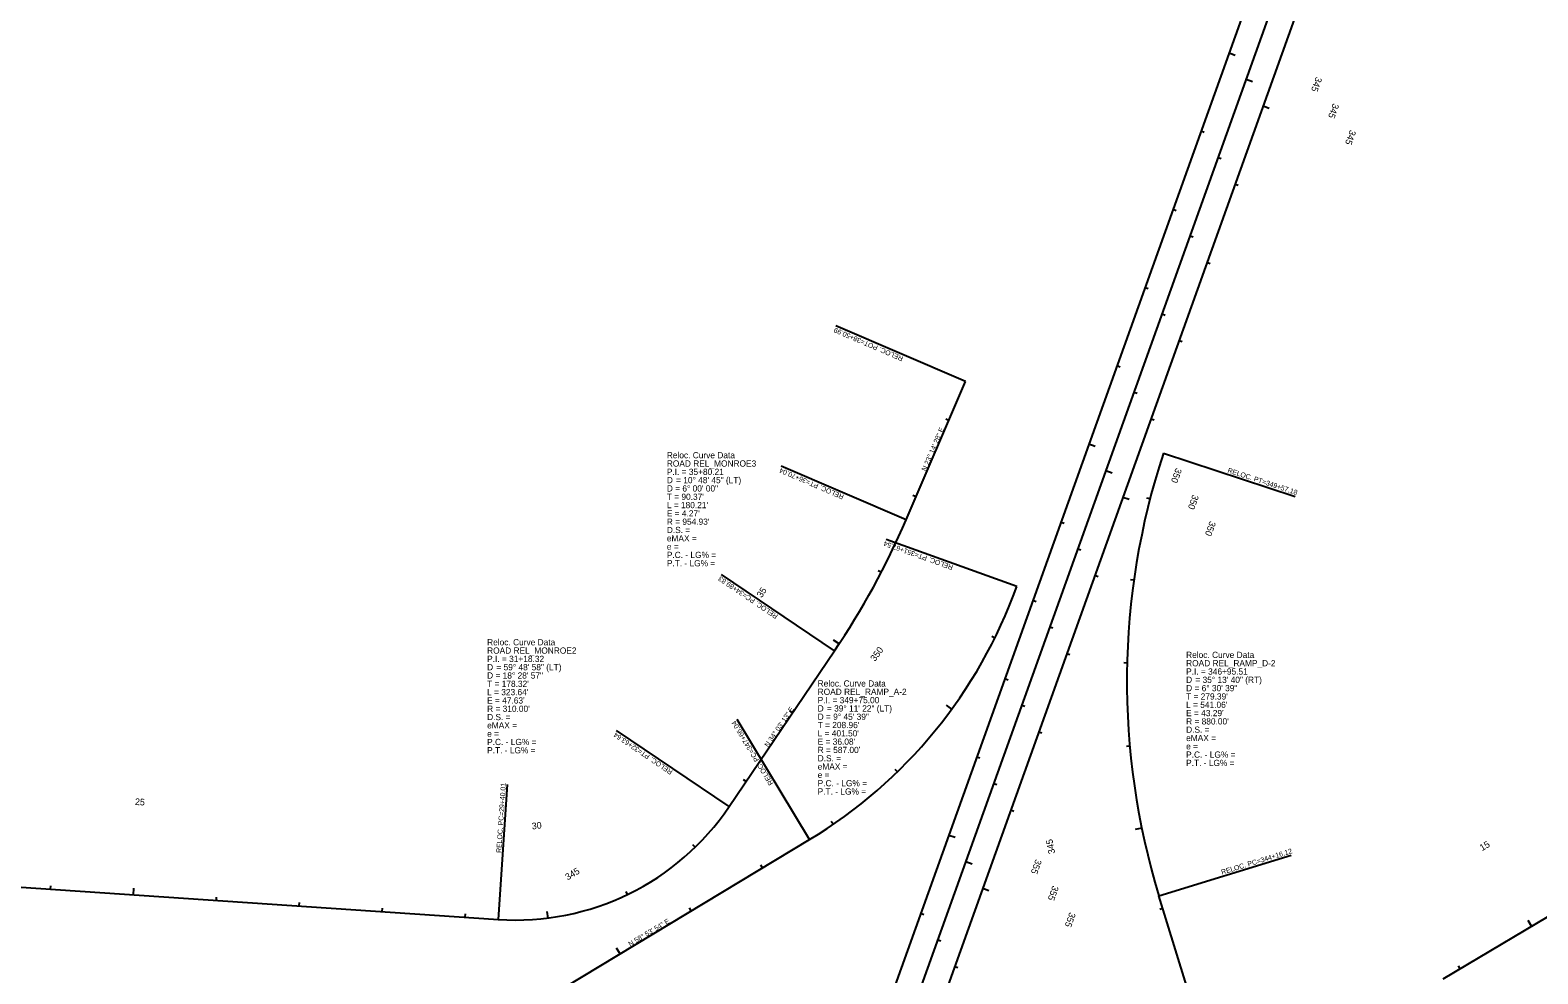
# Model space of a CAD drawing. Extents: x 1902569 to 1961902, y 757103 to 798350.
# Drawn here: x 1940075 to 1941889, y 781155 to 782290 of the extents above; entities that cross this region are included whole.
import ezdxf

# ---------------------------------------------------------------- set-up
doc = ezdxf.new("R2010")
doc.units = 0
for name, color, linetype in [('RD_HC_CL_Rel', 7, 'Continuous'), ('RD_HC_Data_Rel', 7, 'Continuous'), ('RD_HC_Data_Tic_Rel', 7, 'Continuous'), ('RD_HC_TX_Rel_Sta50', 7, 'Continuous')]:
    doc.layers.add(name, color=color, linetype=linetype)

msp = doc.modelspace()

# ---------------------------------------------------------------- linework, layer by layer
at = {"layer": 'RD_HC_CL_Rel'}
for p, q in [((1941878, 783269.7), (1940313.2, 778901.6)), ((1941633, 782497), (1940341.4, 778891.4)), ((1941661.2, 782486.8), (1940101.7, 778133.2)), ((1941128.7, 781701), (1941200.1, 781867.3)), ((1940915.8, 781355.7), (1941042.5, 781543.1)), ((1941774.7, 781148.4), (1942162.1, 781379.3)), ((1939412.5, 781302.9), (1940638.1, 781220)), ((1940629.7, 781085.3), (1941012.4, 781316.1)), ((1941538.5, 780904.1), (1941432.9, 781248.5))]:
    msp.add_line(p, q, dxfattribs=at)
for centre, radius, start, end in [((1942274.3, 781506.4), 880, 161.8185, 197.0463), ((1940251.3, 782077.8), 954.9, 325.9463, 336.7589), ((1940709.2, 781818.7), 587, 301.1016, 340.2909), ((1940659, 781529.3), 310, 266.1303, 325.9463)]:
    msp.add_arc(centre, radius, start, end, dxfattribs=at)
at = {"layer": 'RD_HC_Data_Rel'}
for p, q in [((1941200.1, 781867.3), (1941044.3, 781934.2)), ((1941438.2, 781781), (1941596.6, 781729)), ((1941128.7, 781701), (1940978.4, 781765.5)), ((1941261.8, 781620.8), (1941104.7, 781677)), ((1941042.5, 781543.1), (1940906.5, 781634.9)), ((1940915.8, 781355.7), (1940780.3, 781447.3)), ((1941012.4, 781316.1), (1940925.3, 781460.5)), ((1940638.1, 781220), (1940649, 781382.4)), ((1941432.9, 781248.5), (1941592, 781297.2))]:
    msp.add_line(p, q, dxfattribs=at)
at = {"layer": 'RD_HC_Data_Tic_Rel'}
for p, q in [((1941517.3, 782262.9), (1941524.8, 782260.2)), ((1941537.7, 782231), (1941545.3, 782228.3)), ((1941558.1, 782199), (1941565.7, 782196.3)), ((1941483.6, 782168.8), (1941487.3, 782167.5)), ((1941504, 782136.9), (1941507.8, 782135.5)), ((1941524.4, 782104.9), (1941528.2, 782103.6)), ((1941449.9, 782074.7), (1941453.6, 782073.3)), ((1941470.3, 782042.7), (1941474, 782041.4)), ((1941490.7, 782010.8), (1941494.5, 782009.4)), ((1941416.1, 781980.5), (1941419.9, 781979.2)), ((1941436.6, 781948.6), (1941440.3, 781947.2)), ((1941457, 781916.6), (1941460.7, 781915.3)), ((1941382.4, 781886.4), (1941386.2, 781885)), ((1941402.8, 781854.4), (1941406.6, 781853.1)), ((1941180, 781820.4), (1941176.3, 781822)), ((1941423.2, 781822.5), (1941427, 781821.1)), ((1941348.7, 781792.2), (1941356.2, 781789.5)), ((1941369.1, 781760.3), (1941376.6, 781757.6)), ((1941140.6, 781728.5), (1941136.9, 781730.1)), ((1941389.5, 781728.3), (1941397.1, 781725.6)), ((1941422.2, 781726.1), (1941418.3, 781727.1)), ((1941315, 781698.1), (1941318.7, 781696.7)), ((1941335.4, 781666.1), (1941339.1, 781664.8)), ((1941098.8, 781637.7), (1941095.2, 781639.5)), ((1941355.8, 781634.2), (1941359.6, 781632.8)), ((1941402.7, 781628.1), (1941398.8, 781628.7)), ((1941281.2, 781604), (1941285, 781602.6)), ((1941301.7, 781572), (1941305.4, 781570.7)), ((1941048.1, 781551.5), (1941041.4, 781555.9)), ((1941235.4, 781558.6), (1941231.8, 781560.4)), ((1941322.1, 781540.1), (1941325.8, 781538.7)), ((1941394.6, 781528.5), (1941390.6, 781528.6)), ((1941247.5, 781509.8), (1941251.3, 781508.5)), ((1940992.2, 781468.7), (1940988.9, 781470.9)), ((1941183.7, 781473.2), (1941177.2, 781477.9)), ((1941267.9, 781477.9), (1941271.7, 781476.5)), ((1941288.3, 781445.9), (1941292.1, 781444.6)), ((1941397.7, 781428.6), (1941393.7, 781428.2)), ((1941213.8, 781415.7), (1941217.5, 781414.3)), ((1941118.2, 781397.7), (1941115.4, 781400.6)), ((1940936.2, 781385.8), (1940932.9, 781388)), ((1941234.2, 781383.7), (1941238, 781382.4)), ((1941040.9, 781334.5), (1941038.7, 781337.8)), ((1941254.6, 781351.8), (1941258.4, 781350.4)), ((1941180.1, 781321.5), (1941187.6, 781318.8)), ((1941412.2, 781329.7), (1941404.4, 781328.1)), ((1940875, 781307), (1940872.2, 781309.8)), ((1940955.8, 781282), (1940953.8, 781285.4)), ((1941200.5, 781289.6), (1941208, 781286.9)), ((1940099.3, 781256.4), (1940099.5, 781260.4)), ((1940199, 781249.7), (1940199.6, 781257.7)), ((1940298.8, 781242.9), (1940299.1, 781246.9)), ((1940793.4, 781249.9), (1940791.7, 781253.5)), ((1941220.9, 781257.6), (1941228.4, 781254.9)), ((1940398.6, 781236.2), (1940398.9, 781240.2)), ((1940498.4, 781229.4), (1940498.6, 781233.4)), ((1940598.1, 781222.7), (1940598.4, 781226.7)), ((1940697.9, 781221.7), (1940696.9, 781229.7)), ((1940870.2, 781230.3), (1940868.1, 781233.8)), ((1941146.3, 781227.4), (1941150.1, 781226)), ((1941437.7, 781233), (1941433.8, 781231.9)), ((1941881.2, 781211.9), (1941877.1, 781218.7)), ((1941166.8, 781195.4), (1941170.5, 781194.1)), ((1940784.6, 781178.7), (1940780.4, 781185.5)), ((1941187.2, 781163.5), (1941190.9, 781162.1)), ((1941795.3, 781160.7), (1941793.3, 781164.1))]:
    msp.add_line(p, q, dxfattribs=at)

# ---------------------------------------------------------------- texts
at = {"layer": 'RD_HC_Data_Rel'}
for s, rotation, p in [('RELOC. POT=38+50.99', 156.7589, (1941125.8, 781897)), ('N 23° 14\' 28" E', 66.7589, (1941152.5, 781758.9)), ('RELOC. PT=36+70.04', 156.7589, (1941054.4, 781730.7)), ('RELOC. PT=349+57.18', 341.8185, (1941514.9, 781758)), ('RELOC. PT=351+67.54', 160.2909, (1941185.8, 781645.9)), ('RELOC. PC=34+89.83', 145.9463, (1940975.1, 781586.2)), ('N 34° 03\' 13" E', 55.9463, (1940962.7, 781426.8)), ('RELOC. PC=347+66.04', 121.1016, (1940969.3, 781383.6)), ('RELOC. PT=32+63.64', 145.9463, (1940848.4, 781398.8)), ('RELOC. PC=29+40.01', 86.1303, (1940641.5, 781299.9)), ('RELOC. PC=344+16.12', 17.0463, (1941508.8, 781273.8)), ('N 58° 53\' 54" E', 31.1016, (1940796.7, 781187.2))]:
    msp.add_text(s, height=6, rotation=rotation, dxfattribs=at).set_placement(p)
for s, p in [('Reloc. Curve Data', (1940840.8, 781774.9)), ('ROAD REL_MONROE3', (1940840.8, 781764.9)), ('P.I. = 35+80.21', (1940840.8, 781754.9)), ('D', (1940840.8, 781744.9)), ('    = 10° 48\' 45" (LT)', (1940840.8, 781744.9)), ('D = 6° 00\' 00"', (1940840.8, 781734.9)), ("T = 90.37'", (1940840.8, 781724.9)), ("L = 180.21'", (1940840.8, 781714.9)), ("E = 4.27'", (1940840.8, 781704.9)), ("R = 954.93'", (1940840.8, 781694.9)), ('eMAX = ', (1940840.8, 781674.9)), ('D.S. =', (1940840.8, 781684.9)), ('e = ', (1940840.8, 781664.9)), ('P.C. - LG% = ', (1940840.8, 781654.9)), ('P.T. - LG% = ', (1940840.8, 781644.9)), ('Reloc. Curve Data', (1940624.6, 781549.8)), ('ROAD REL_MONROE2', (1940624.6, 781539.8)), ('P.I. = 31+18.32', (1940624.6, 781529.8)), ('Reloc. Curve Data', (1941465.6, 781534.6)), ('D', (1940624.6, 781519.8)), ('D = 18° 28\' 57"', (1940624.6, 781509.8)), ('    = 59° 48\' 58" (LT)', (1940624.6, 781519.8)), ('ROAD REL_RAMP_D-2', (1941465.6, 781524.6)), ('P.I. = 346+95.51', (1941465.6, 781514.6)), ("T = 178.32'", (1940624.6, 781499.8)), ('Reloc. Curve Data', (1941022.3, 781500.2)), ('D', (1941465.6, 781504.6)), ('D = 6° 30\' 39"', (1941465.6, 781494.6)), ('    = 35° 13\' 40" (RT)', (1941465.6, 781504.6)), ("L = 323.64'", (1940624.6, 781489.8)), ("E = 47.63'", (1940624.6, 781479.8)), ('ROAD REL_RAMP_A-2', (1941022.3, 781490.2)), ('P.I. = 349+75.00', (1941022.3, 781480.2)), ("T = 279.39'", (1941465.6, 781484.6)), ("L = 541.06'", (1941465.6, 781474.6)), ("R = 310.00'", (1940624.6, 781469.8)), ('D.S. =', (1940624.6, 781459.8)), ('D', (1941022.3, 781470.2)), ('D = 9° 45\' 39"', (1941022.3, 781460.2)), ('    = 39° 11\' 22" (LT)', (1941022.3, 781470.2)), ("E = 43.29'", (1941465.6, 781464.6)), ("R = 880.00'", (1941465.6, 781454.6)), ('eMAX = ', (1940624.6, 781449.8)), ('e = ', (1940624.6, 781439.8)), ("T = 208.96'", (1941022.3, 781450.2)), ("L = 401.50'", (1941022.3, 781440.2)), ('D.S. =', (1941465.6, 781444.6)), ('P.C. - LG% = ', (1940624.6, 781429.8)), ('P.T. - LG% = ', (1940624.6, 781419.8)), ("E = 36.08'", (1941022.3, 781430.2)), ("R = 587.00'", (1941022.3, 781420.2)), ('eMAX = ', (1941465.6, 781434.6)), ('e = ', (1941465.6, 781424.6)), ('D.S. =', (1941022.3, 781410.2)), ('P.C. - LG% = ', (1941465.6, 781414.6)), ('P.T. - LG% = ', (1941465.6, 781404.6)), ('eMAX = ', (1941022.3, 781400.2)), ('e = ', (1941022.3, 781390.2)), ('P.C. - LG% = ', (1941022.3, 781380.2)), ('P.T. - LG% = ', (1941022.3, 781370.2))]:
    msp.add_text(s, height=7.5, dxfattribs=at).set_placement(p)
at = {"layer": 'RD_HC_TX_Rel_Sta50'}
for s, rotation, p in [('345', 250.2909, (1941621.8, 782234.5)), ('345', 250.2909, (1941642.3, 782202.6)), ('345', 250.2909, (1941662.7, 782170.6)), ('350', 250.2909, (1941453.2, 781763.8)), ('350', 250.2909, (1941473.6, 781731.9)), ('350', 250.2909, (1941494.1, 781699.9)), ('35', 56.5563, (1940954.9, 781606.4)), ('350', 53.9377, (1941091.4, 781529.9)), ('25', 356.1303, (1940200.7, 781357.8)), ('30', 7.2183, (1940678.8, 781328.2)), ('345', 101.5849, (1941308.1, 781299.7)), ('15', 30.7968, (1941821.7, 781302.1)), ('345', 31.1016, (1940721.5, 781266.8)), ('355', 250.2909, (1941284.6, 781293.1)), ('355', 250.2909, (1941305, 781261.2)), ('355', 250.2909, (1941325.4, 781229.2))]:
    msp.add_text(s, height=8, rotation=rotation, dxfattribs=at).set_placement(p)

doc.saveas('drawing.dxf')
